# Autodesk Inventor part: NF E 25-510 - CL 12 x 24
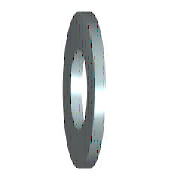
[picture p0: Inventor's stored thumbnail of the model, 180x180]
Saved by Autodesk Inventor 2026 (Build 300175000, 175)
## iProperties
Created: 2025-01
Part Number: NF E 25-510 - CL 12 x 24
Material: Acier, doux
Description: Rondelles cuvette
Document SubType Name: Modeling
Standard: NF E 25-510
Designer: thierry.jost
Standards Organization: AFNOR
Language: fr-FR
Size Designation: CL 12 x 24
Categories: <MemberInstance><Categories><Category DisplayName="Visserie" InternalName="e4da775c-781d-43d5-af7c-5136215cf5a6" Mnemonic="FSTN"><Category DisplayName="Rondelle
Density: 7.85 g/cm^3
Appearance: Semi-poli
IsCustomPart: 0
Author: thierry.jost
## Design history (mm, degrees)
workaxis "Work Axis1"
workplane "Work Plane1"
body "Solid1"
sketch "Esquisse"
  geometry: C1 r 12 at (0, 0); C2 r 6.5 at (0, 0); 1 further point
  constraints: 2 centre point, 2 coincident
  dimensions: "d0" = 13 diameter of C2 (= SD1); "d1" = 24 diameter of C1 (= SD2)
extrude "Corps" new body sketch "Esquisse" distance "d2" = 2.8 (= SD); taper "d3" = 0 deg
other parameters: "SD1" = 13 [user parameter; used in 1 equation term], "SD2" = 24 [user parameter; used in 1 equation term], "SD" = 2.8 [user parameter; used in 1 equation term], "d4" = 0, "d5" = 0, "d6" = 0, "d7" = 0, "NND" = 12 [user parameter]
